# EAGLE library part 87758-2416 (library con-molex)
24 Pin - 2mm Dual Row Single Wafer, Vertical T/H HDR Source: http://www.molex.com/pdm_docs/sd/877580616_sd.pdf
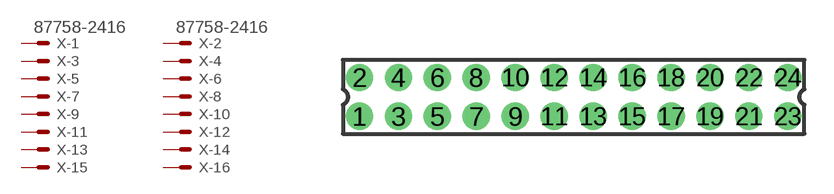
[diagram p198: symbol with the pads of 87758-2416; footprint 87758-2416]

Designator prefix X; gates -1=MV -2=MV -3=M -4=M -5=M -6=M -7=M -8=M -9=M -10=M -11=M -12=M -13=M -14=M -15=M -16=M -17=M -18=M -19=M -20=M -21=M -22=M -23=M -24=M

## 87758-2416 (MPN: 87758-2416; OC_FARNELL: unknown; OC_NEWARK: 25M5679)  [87758-2416]
1  -1:S  pas
2  -2:S  pas
3  -3:S  pas
4  -4:S  pas
5  -5:S  pas
6  -6:S  pas
7  -7:S  pas
8  -8:S  pas
9  -9:S  pas
10  -10:S  pas
11  -11:S  pas
12  -12:S  pas
13  -13:S  pas
14  -14:S  pas
15  -15:S  pas
16  -16:S  pas
17  -17:S  pas
18  -18:S  pas
19  -19:S  pas
20  -20:S  pas
21  -21:S  pas
22  -22:S  pas
23  -23:S  pas
24  -24:S  pas

## Footprint 87758-2416 (pad centres in mm)
24 Pin - 2mm Dual Row Single Wafer, Vertical T/H HDR Source: http://www.molex.com/pdm_docs/sd/877580616_sd.pdf
drill 0.9 pad 1.27 round: 1 -11,-1; 2 -11,1; 3 -9,-1; 4 -9,1; 5 -7,-1; 6 -7,1; 7 -5,-1; 8 -5,1; 9 -3,-1; 10 -3,1; 11 -1,-1; 12 -1,1; 13 1,-1; 14 1,1; 15 3,-1; 16 3,1; 17 5,-1; 18 5,1; 19 7,-1; 20 7,1; 21 9,-1; 22 9,1; 23 11,-1; 24 11,1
